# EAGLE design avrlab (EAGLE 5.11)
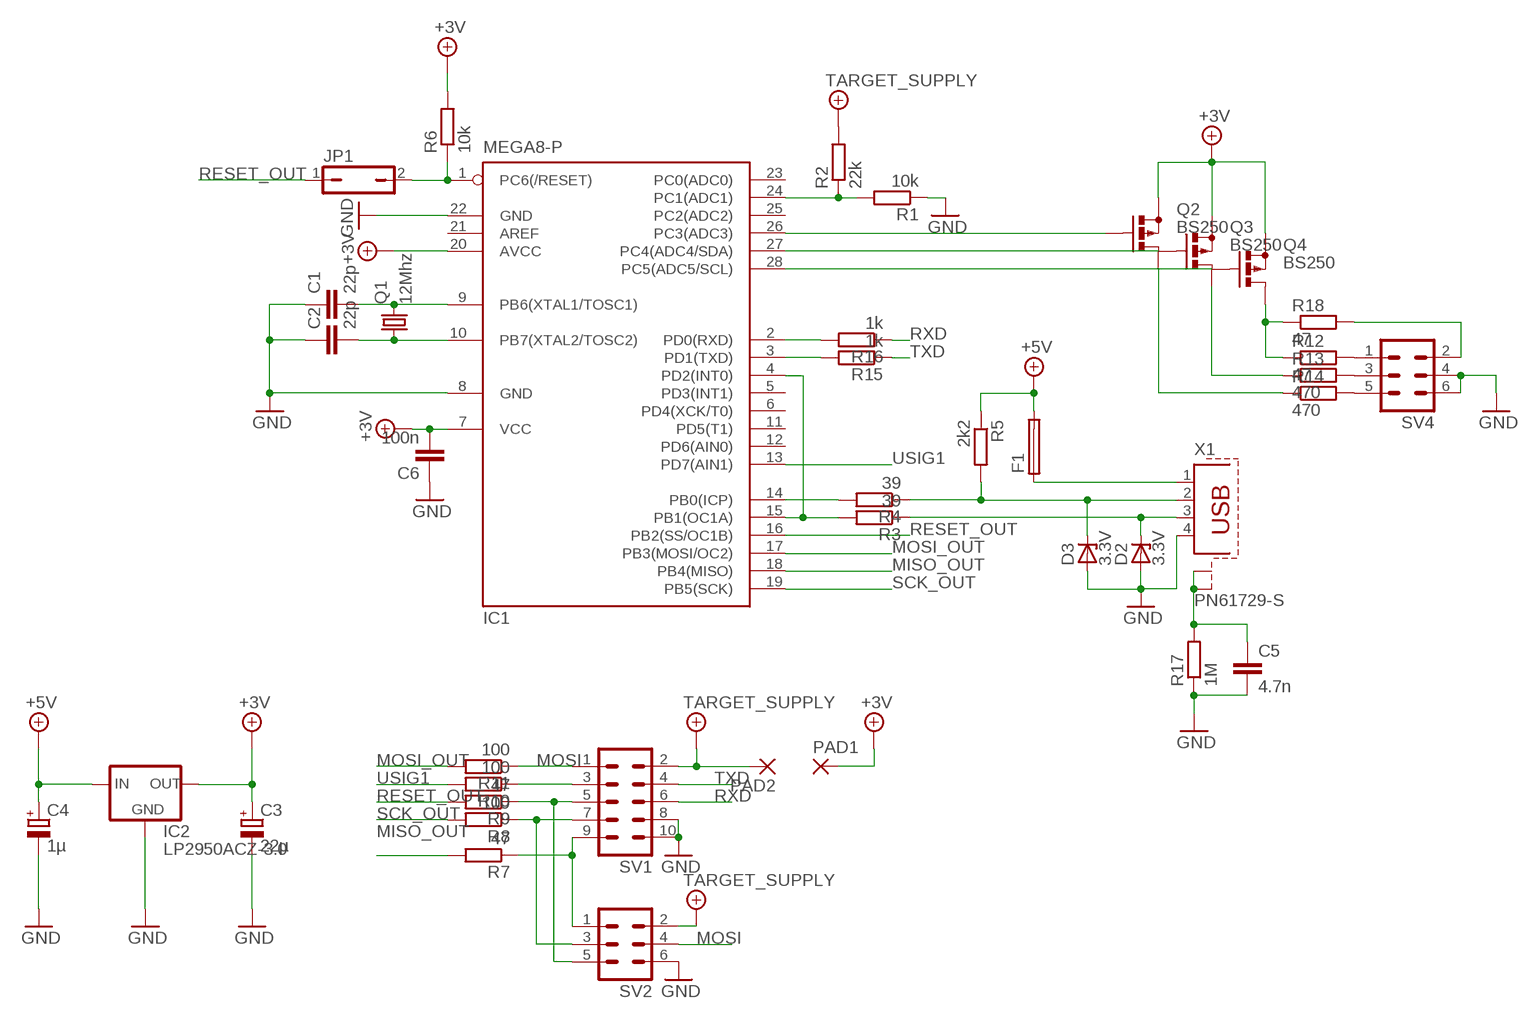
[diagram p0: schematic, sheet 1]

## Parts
C1  22p  C-EU025-025X050  [C025-025X050]
C2  22p  C-EU025-025X050  [C025-025X050]
C3  22µ  CPOL-EUE2.5-5  [E2,5-5]
C4  1µ  CPOL-EUE2.5-5  [E2,5-5]
C5  4.7n  C-EU050-025X075  [C050-025X075]
C6  100n  C-EU025-025X050  [C025-025X050]
D2  3.3V  ZENER-DIODEDO34-7  [DO34Z7]
D3  3.3V  ZENER-DIODEDO34-7  [DO34Z7]
F1  POLYFUSE_RM5  [POLYFUSE_RM5]
IC1  MEGA8-P  [DIL28-3]
IC2  LP2950ACZ-3.0  [TO92]
JP1  JP1Q  [JP1]
PAD1  WIREPAD2,54/1,1  [2,54/1,1]
PAD2  WIREPAD2,54/1,1  [2,54/1,1]
Q1  12Mhz  CRYSTALHC49S  [HC49/S]
Q2  BS250  [SOT54E]
Q3  BS250  [SOT54E]
Q4  BS250  [SOT54E]
R1  10k  R-EU_0204/7  [0204/7]
R2  22k  R-EU_0204/7  [0204/7]
R3  39  R-EU_0204/7  [0204/7]
R4  39  R-EU_0204/7  [0204/7]
R5  2k2  R-EU_0204/7  [0204/7]
R6  10k  R-EU_0204/7  [0204/7]
R7  47  R-EU_0204/7  [0204/7]
R8  100  R-EU_0204/7  [0204/7]
R9  47  R-EU_0207/10  [0207/10]
R10  100  R-EU_0204/7  [0204/7]
R11  100  R-EU_0204/7  [0204/7]
R12  47  R-EU_0204/7  [0204/7]
R13  470  R-EU_0204/7  [0204/7]
R14  470  R-EU_0204/7  [0204/7]
R15  1k  R-EU_0204/7  [0204/7]
R16  1k  R-EU_0204/7  [0204/7]
R17  1M  R-EU_0204/7  [0204/7]
R18  47  R-EU_0204/7  [0204/7]
SV1  ML10L  [ML10L]
SV2  ML6L  [ML6L]
SV4  ML6  [ML6]
X1  PN61729-S  [PN61729-S]

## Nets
+3V: C3.+ C6.2 IC1.7(VCC) IC1.20(AVCC) IC2.1(OUT) PAD1.1(P) Q2.S Q3.S Q4.S R6.2
+5V: C4.+ F1.2 IC2.3(IN) R5.1
GND: C1.1 C2.1 C3.- C4.- C5.2 C6.1 D2.A D3.A IC1.8(GND) IC1.22(GND) IC2.2(GND) R1.1 R17.1 SV1.8 SV1.10 SV2.6 SV4.4 SV4.6 X1.4
MISO_OUT: IC1.18(PB4(MISO)) R7.2
MOSI: R11.1 SV1.1 SV2.4
MOSI_OUT: IC1.17(PB3(MOSI/OC2)) R11.2
N$1: IC1.24(PC1(ADC1)) R1.2 R2.1
N$2: C2.2 IC1.10(PB7(XTAL2/TOSC2)) Q1.1
N$3: C1.2 IC1.9(PB6(XTAL1/TOSC1)) Q1.2
N$4: IC1.1(PC6(/RESET)) JP1.2 R6.1
N$5: IC1.14(PB0(ICP)) R4.2
N$6: D3.C R4.1 R5.2 X1.2
N$7: D2.C R3.1 X1.3
N$8: IC1.4(PD2(INT0)) IC1.15(PB1(OC1A)) R3.2
N$9: Q2.D R14.1
N$10: IC1.2(PD0(RXD)) R16.2
N$11: R10.1 SV1.3
N$12: Q4.D R12.1 R18.1
N$13: R8.1 SV1.7 SV2.3
N$14: R7.1 SV1.9 SV2.1
N$15: IC1.26(PC3(ADC3)) Q2.G
N$16: R14.2 SV4.5
N$17: IC1.27(PC4(ADC4/SDA)) Q3.G
N$18: IC1.28(PC5(ADC5/SCL)) Q4.G
N$19: F1.1 X1.1
N$20: R12.2 SV4.1
N$21: R13.2 SV4.3
N$22: IC1.3(PD1(TXD)) R15.2
N$23: R9.1 SV1.5 SV2.5
N$24: Q3.D R13.1
N$25: C5.1 R17.2 X1.S1 X1.S2
N$26: R18.2 SV4.2
RESET_OUT: IC1.16(PB2(SS/OC1B)) JP1.1 R9.2
RXD: R16.1 SV1.6
SCK_OUT: IC1.19(PB5(SCK)) R8.2
TARGET_SUPPLY: PAD2.1(P) R2.2 SV1.2 SV2.2
TXD: R15.1 SV1.4
USIG1: IC1.13(PD7(AIN1)) R10.2
Unconnected: IC1.5(PD3(INT1)) IC1.6(PD4(XCK/T0)) IC1.11(PD5(T1)) IC1.12(PD6(AIN0)) IC1.21(AREF) IC1.23(PC0(ADC0)) IC1.25(PC2(ADC2))

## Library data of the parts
C1 C2 C5 C6 = rcl:C-EU: CAPACITOR, European symbol
C3 C4 = rcl:CPOL-EU: POLARIZED CAPACITOR, European symbol
D2 D3 = diode:ZENER-DIODE: Z-Diode
F1 = olli:POLYFUSE_RM5: Polyfuse; REICHELT: PFRA
IC1 = atmel:MEGA8-P: MICROCONTROLLER 8 Kbytes FLASH, 1 kbytes SRAM, 512 bytes EEPROM, USART, 4-channel 10 bit ADC, 2-channel 8 bit ADC Pin compatible with Atmega48, ATMega88, ATMega168 Source: avr.lbr; OC_FARNELL: unknown; OC_NEWARK: unknown
IC2 = v-reg:LP2950?*: Source: http://cache.national.com/ds/LP/LP2950.pdf
JP1 = jumper:JP1Q: JUMPER
PAD1 PAD2 = wirepad:WIREPAD: Wire PAD connect wire on PCB
Q1 = crystal:CRYSTAL: CRYSTAL; OC_FARNELL: 1667008; OC_NEWARK: unknown
Q2-Q4 = transistor-small-signal:BS250: P-CHANNEL MOS FET
R1-R18 = rcl:R-EU_: RESISTOR, European symbol
SV1 = con-ml:ML10L: HARTING; OC_FARNELL: unknown; OC_NEWARK: unknown
SV2 = con-ml:ML6L: HARTING; OC_FARNELL: unknown; OC_NEWARK: unknown
SV4 = con-harting-ml:ML6: HARTING; OC_FARNELL: unknown; OC_NEWARK: unknown
X1 = con-berg:PN61729-S: BERG USB connector; OC_FARNELL: unknown; OC_NEWARK: unknown

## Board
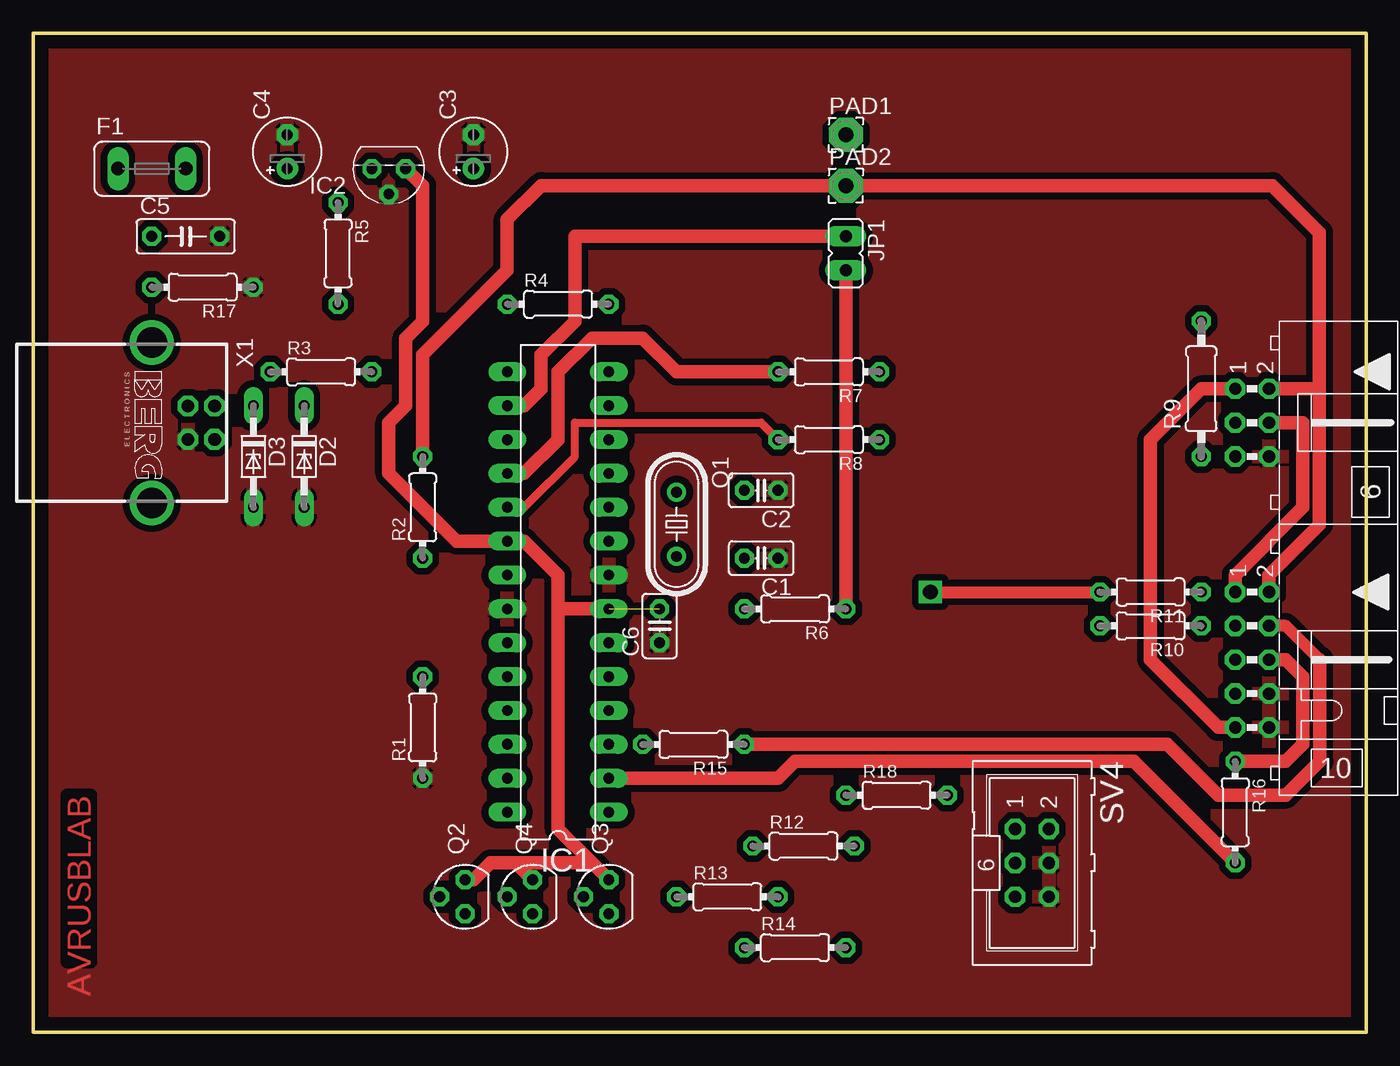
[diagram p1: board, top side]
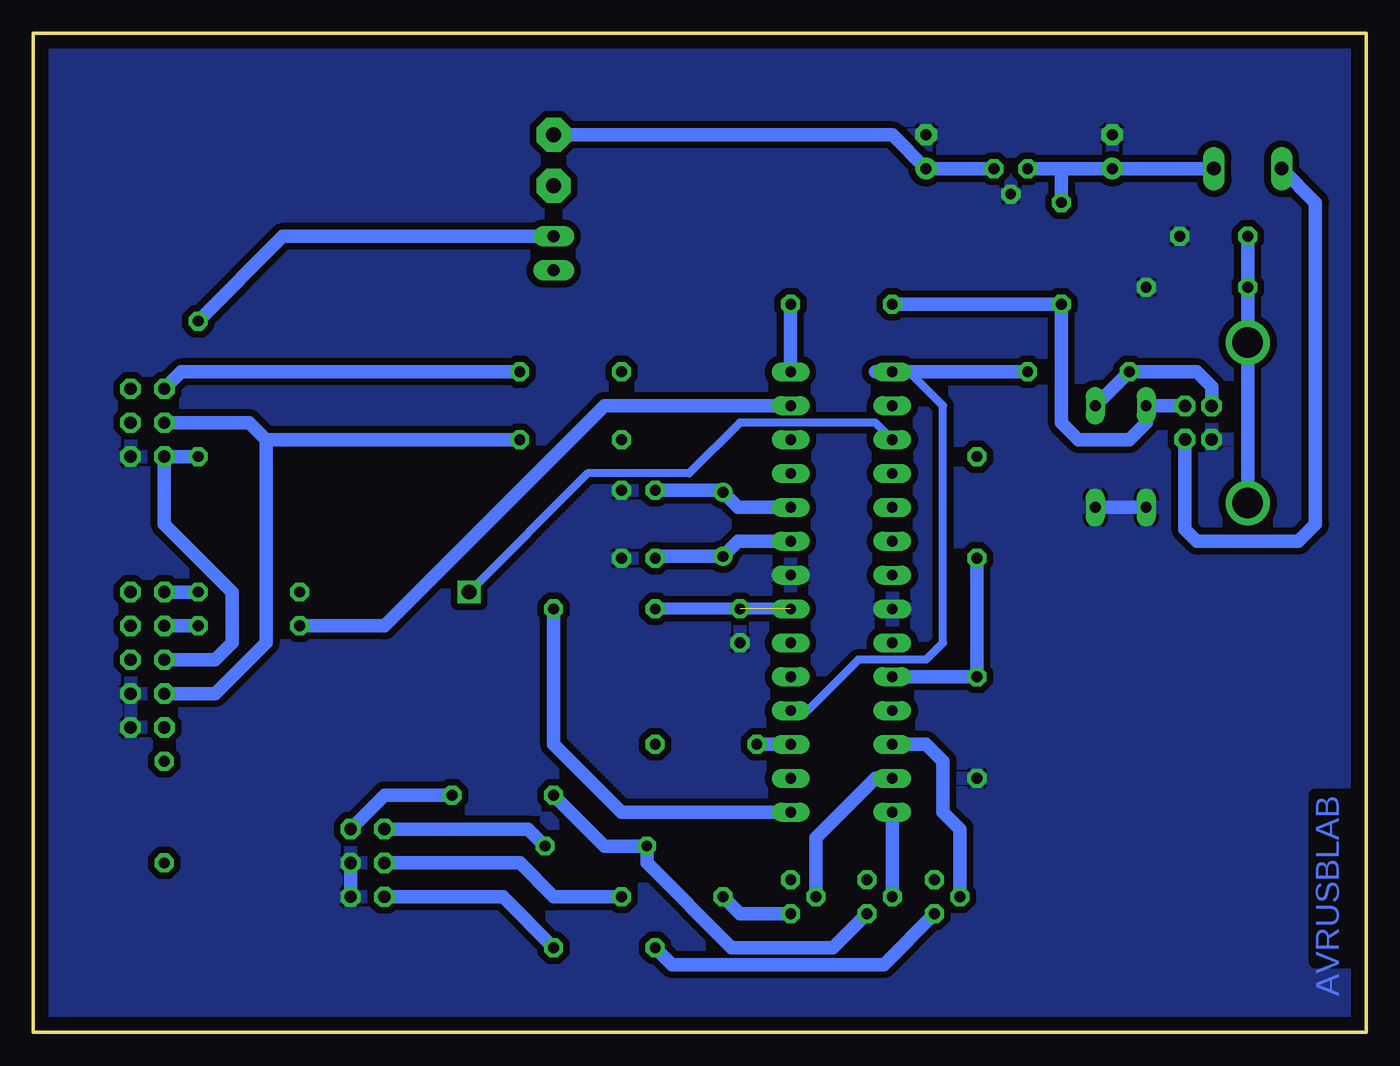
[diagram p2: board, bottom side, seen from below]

Size 100 x 74.92 mm. Coordinates in mm from the lower left corner, seen from the top.
Outline: 0,0 100,0 100,74.92 0,74.92 0,0
Copper layers (1*16): Top 0.035mm / dielectric 1.5mm / Bottom 0.035mm
Design rules "default *": minimum track width 10mil, minimum drill 24mil, track to track 0.2mm, track to pad 8mil, pad to pad 8mil, via to via 8mil, smd to smd 8mil, copper to edge 40mil, drill to drill 8mil, minimum pad ring 12mil, minimum via ring 12mil, stop-mask expansion 4mil, vias tented up to drill 0mil, thermal gap 10mil

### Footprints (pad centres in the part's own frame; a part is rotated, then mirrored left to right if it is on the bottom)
C025-025X050 = drill 0.813 octagon: 1 -1.27,0; 2 1.27,0
E2,5-5 = drill 0.813 pad 1.6 round: + -1.27,0 | drill 0.813 pad 1.6 octagon: - 1.27,0
C050-025X075 = drill 0.813 octagon: 1 -2.54,0; 2 2.54,0
DO34Z7 = drill 0.813 long: A 3.81,0; C -3.81,0
POLYFUSE_RM5 = drill 1.016 long: 1 -2.54,0; 2 2.54,0
DIL28-3 = drill 0.813 long: 1 -16.51,-3.81; 2 -13.97,-3.81; 3 -11.43,-3.81; 4 -8.89,-3.81; 5 -6.35,-3.81; 6 -3.81,-3.81; 7 -1.27,-3.81; 8 1.27,-3.81; 9 3.81,-3.81; 10 6.35,-3.81; 11 8.89,-3.81; 12 11.43,-3.81; 13 13.97,-3.81; 14 16.51,-3.81; 15 16.51,3.81; 16 13.97,3.81; 17 11.43,3.81; 18 8.89,3.81; 19 6.35,3.81; 20 3.81,3.81; 21 1.27,3.81; 22 -1.27,3.81; 23 -3.81,3.81; 24 -6.35,3.81; 25 -8.89,3.81; 26 -11.43,3.81; 27 -13.97,3.81; 28 -16.51,3.81
TO92 = drill 0.813 octagon: 1 -1.27,0; 2 0,1.905; 3 1.27,0
JP1 = drill 0.914 long: 1 0,-1.27; 2 0,1.27
2,54/1,1 = drill 1.118 pad 2.54 octagon: 1 0,0
HC49/S = drill 0.813 round: 1 -2.413,0; 2 2.413,0
SOT54E = drill 0.813 octagon: D -1.27,0; G 0,1.905; S 1.27,0
0204/7 = drill 0.813 octagon: 1 -3.81,0; 2 3.81,0
0207/10 = drill 0.813 octagon: 1 -5.08,0; 2 5.08,0
ML10L = drill 0.914 octagon: 1 -5.08,-1.27; 2 -5.08,1.27; 3 -2.54,-1.27; 4 -2.54,1.27; 5 0,-1.27; 6 0,1.27; 7 2.54,-1.27; 8 2.54,1.27; 9 5.08,-1.27; 10 5.08,1.27
ML6L = drill 0.914 octagon: 1 -2.54,-1.27; 2 -2.54,1.27; 3 0,-1.27; 4 0,1.27; 5 2.54,-1.27; 6 2.54,1.27
ML6 = drill 0.914 octagon: 1 -2.54,-1.27; 2 -2.54,1.27; 3 0,-1.27; 4 0,1.27; 5 2.54,-1.27; 6 2.54,1.27
PN61729-S = drill 0.95 octagon: 1 1.25,4.71; 2 -1.25,4.71; 3 -1.25,2.71; 4 1.25,2.71 | drill 2.3 pad 2.9 round: S1 -6.02,0; S2 6.02,0

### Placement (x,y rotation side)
C1  54.61,35.56 180 top
C2  54.61,40.64 180 top
C3  33.02,66.04 90 top
C4  19.05,66.04 90 top
C5  11.43,59.69 0 top
C6  46.99,30.48 90 top
D2  20.32,43.18 270 top
D3  16.51,43.18 270 top
F1  8.89,64.77 0 top
IC1  39.37,33.02 90 top
IC2  26.67,64.77 180 top
JP1  60.96,58.42 180 top
PAD1  60.96,67.31 0 top
PAD2  60.96,63.5 0 top
Q1  48.26,38.1 270 top
Q2  32.38,10.16 90 top
Q3  43.18,10.16 90 top
Q4  37.47,10.16 90 top
R1  29.21,22.86 90 top
R2  29.21,39.37 90 top
R3  21.59,49.53 0 top
R4  39.37,54.61 0 top
R5  22.86,58.42 270 top
R6  57.15,31.75 180 top
R7  59.69,49.53 180 top
R8  59.69,44.45 180 top
R9  87.63,48.26 90 top
R10  83.82,30.48 180 top
R11  83.82,33.02 180 top
R12  57.78,13.97 0 top
R13  52.07,10.16 0 top
R14  57.15,6.35 0 top
R15  49.53,21.59 180 top
R16  90.17,16.51 270 top
R17  12.7,55.88 180 top
R18  64.77,17.78 0 top
SV1  91.44,27.94 270 top
SV2  91.44,45.72 270 top
SV4  74.93,12.7 270 top
X1  8.89,45.72 270 top

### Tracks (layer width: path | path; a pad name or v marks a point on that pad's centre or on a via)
+3V  (1 unrouted)
  Top 1.016: IC2.1 29.21,63.5 29.21,53.34 27.94,52.07 27.94,46.99 26.67,45.72 26.67,41.91 31.75,36.83 IC1.20 36.83,36.83 39.37,34.29 39.37,31.75 | 41.91,12.7 Q3.S | 41.91,12.7 39.37,15.24 39.37,31.75 | 36.2,12.7 Q4.S | 36.2,12.7 34.29,12.7 33.02,11.43 Q2.S | 36.2,12.7 41.91,12.7 | 39.37,31.75 IC1.7
  Bottom 0.91: IC1.7 R6.2
  Bottom 1.016: IC2.1 C3.+ 35.56,67.31 PAD1.1
+5V
  Bottom 1.016: 22.86,64.77 C4.+ F1.2 | 22.86,64.77 IC2.3 | 22.86,64.77 R5.1
GND
  Bottom 1.016: X1.4 11.43,44.3 | D3.A D2.A | SV4.6 SV4.4
  pour Bottom (isolate 0.508): 0,80.01 0,0 100.33,0 100.33,80.01 96.52,80.01
  pour Top (isolate 0.508): 0,80.01 100.33,81.28 100.33,78.74 99.06,78.74 99.06,0 0,0
MISO_OUT
  Top 1.016: R7.2 48.26,49.53 45.72,52.07 41.91,52.07 39.37,49.53 39.37,44.45 36.83,41.91 IC1.18
MOSI
  Top 1.016: SV1.1 90.17,34.29 95.25,39.37 95.25,45.72 SV2.4
  Bottom 1.016: R11.1 SV1.1
MOSI_OUT  (via drill 1.1)
  Top 0.91: v67.31,33.02 R11.2
  Bottom 0.61: IC1.17 36.83,45.72 46.99,45.72 50.8,41.91 58.42,41.91 v67.31,33.02
N$1
  Bottom 1.016: R2.1 R1.2 IC1.24
N$2
  Bottom 1.016: IC1.10 47.12,39.37 Q1.1 48.39,40.64 C2.2
N$3
  Bottom 1.016: IC1.9 47.12,36.83 Q1.2 53.21,35.69 C1.2
N$4
  Top 1.016: R6.1 JP1.2
  Bottom 1.016: IC1.1 55.88,16.51 60.96,21.59 R6.1
N$5
  Bottom 1.016: IC1.14 R4.2
N$6
  Bottom 1.016: X1.2 13.62,46.99 D3.C 16.51,45.72 17.78,44.45 21.59,44.45 22.86,45.72 R5.2 R4.1
N$7
  Bottom 1.016: X1.3 11.6,48.43 12.7,49.53 R3.1 D2.C
N$8
  Bottom 0.61: IC1.4 41.91,24.13 38.1,27.94 33.02,27.94 31.75,29.21 31.75,46.99 34.29,49.53
  Bottom 1.016: 36.83,49.53 IC1.15 34.29,49.53 R3.2
N$9
  Bottom 1.016: R14.1 52.07,5.08 36.2,5.08 Q2.D
N$10
  Top 1.016: IC1.2 55.88,19.05 57.15,20.32 82.55,20.32 R16.2
N$11
  Bottom 1.016: R10.1 SV1.3
N$12
  Bottom 1.016: Q4.D 40.01,6.35 47.62,6.35 53.98,12.7 R12.1 57.15,13.97 R18.1
N$13
  Bottom 1.016: SV1.7 86.36,25.4 82.55,29.21 82.55,44.45 | R8.1 82.55,44.45 | 82.55,44.45 83.82,45.72 SV2.3
N$14
  Top 1.016: SV1.9 88.9,22.86 83.82,27.94 83.82,44.45 87.63,48.26 SV2.1
  Bottom 1.016: R7.1 88.9,49.53 SV2.1
N$15
  Bottom 1.016: IC1.26 33.02,21.59 31.75,20.32 31.75,16.51 30.48,15.24 Q2.G
N$16
  Bottom 1.016: R14.2 64.77,10.16 SV4.5
N$17
  Bottom 1.016: IC1.27 36.83,19.05 41.27,14.61 Q3.G
N$18
  Bottom 1.016: Q4.G IC1.28
N$19
  Bottom 1.016: X1.1 13.6,37.73 12.7,36.83 5.08,36.83 3.81,38.1 3.81,62.23 F1.1
N$20
  Bottom 1.016: R12.2 62.87,15.24 SV4.1
N$21
  Bottom 1.016: R13.2 60.96,10.16 63.5,12.7 SV4.3
N$22
  Bottom 1.016: IC1.3 R15.2
N$23
  Bottom 1.016: R9.1 SV2.5 90.17,38.1 85.09,33.02 85.09,29.21 86.36,27.94 SV1.5
N$24
  Bottom 1.016: Q3.D 46.99,8.89 R13.1
N$25
  Bottom 1.016: C5.1 R17.2 X1.S1 X1.S2
N$26
  Bottom 1.016: SV4.2 73.66,17.78 R18.2
RESET_OUT
  Top 1.016: IC1.16 36.83,46.99 38.1,48.26 38.1,50.8 40.64,53.34 40.64,59.69 JP1.1
  Bottom 1.016: R9.2 81.28,59.69 JP1.1
RXD
  Top 1.016: SV1.6 93.98,27.94 95.25,26.67 95.25,21.59 93.98,20.32 R16.1
SCK_OUT
  Top 0.61: IC1.19 36.83,39.37 40.64,43.18 40.64,45.72 54.61,45.72 R8.2
TARGET_SUPPLY
  Top 1.016: 96.5,48.26 96.5,59.97 92.96,63.5 PAD2.1 38.1,63.5 35.56,60.96 35.56,57.15 29.21,50.8 R2.2 | 96.5,48.26 96.5,38.08 92.71,34.29 SV1.2 | 96.5,48.26 SV2.2
TXD
  Top 0.91: 96.52,27.94 93.98,30.48 SV1.4
  Top 1.016: R15.1 85.09,21.59 88.9,17.78 93.98,17.78 96.52,20.32 96.52,27.94
USIG1
  Bottom 1.016: R10.2 73.66,30.48 57.15,46.99 IC1.13

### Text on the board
Top: AVRUSBLAB
Bottom: AVRUSBLAB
